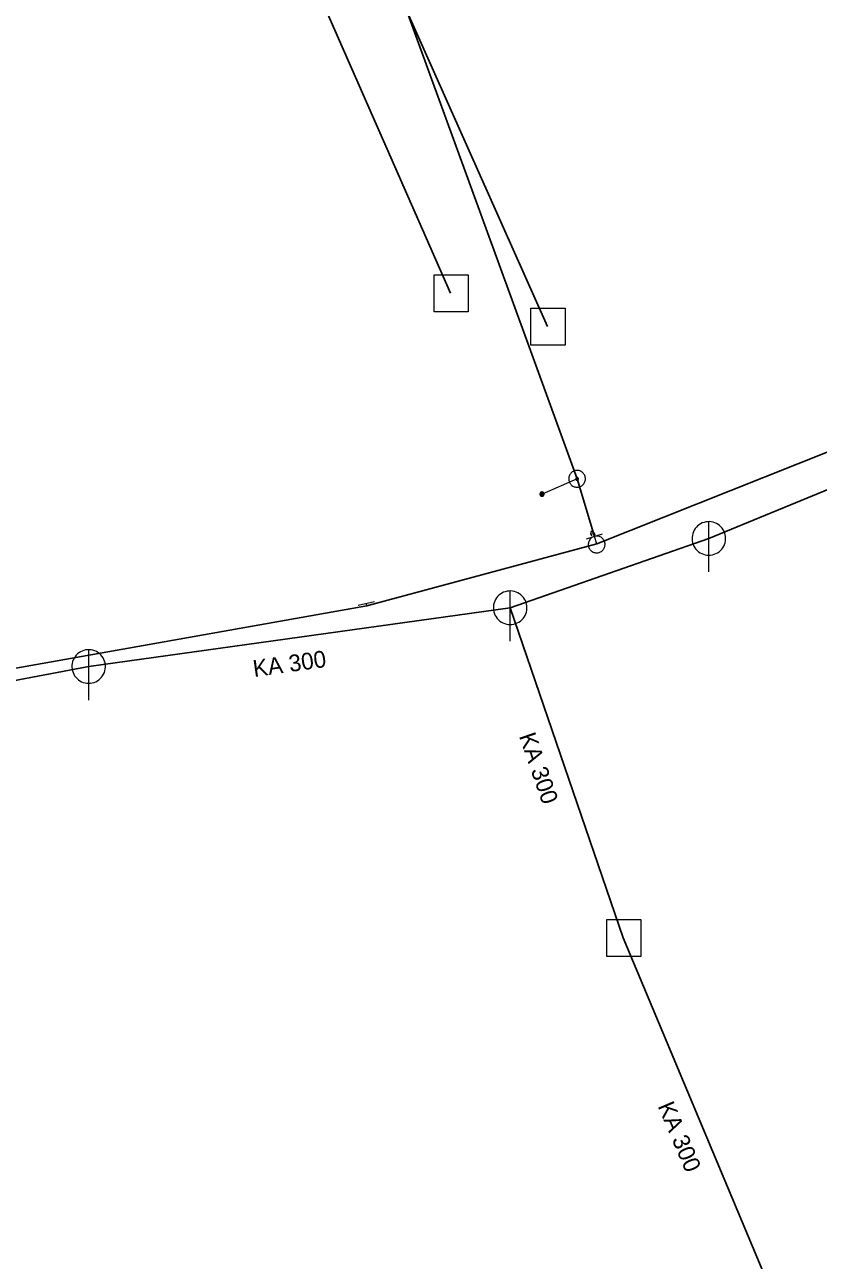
# Model space of a CAD drawing. Extents: x -690535 to -689974, y -975624 to -975325.
# Drawn here: x -690213.7 to -690166.4, y -975472.2 to -975398.6 of the extents above; entities that cross this region are included whole.
import ezdxf

# ---------------------------------------------------------------- set-up
doc = ezdxf.new("R2010")
doc.units = 0
doc.header["$LTSCALE"] = 0.4
for name, color, linetype, lineweight in [('1', 7, 'Continuous', 13), ('14', 7, 'Continuous', 25), ('17', 7, 'Continuous', 25), ('22', 7, 'Continuous', 13), ('23', 7, 'Continuous', 13), ('34', 7, 'Continuous', 13), ('47', 7, 'Continuous', 13), ('9', 7, 'Continuous', 13)]:
    doc.layers.add(name, color=color, linetype=linetype, lineweight=lineweight)

msp = doc.modelspace()

# ---------------------------------------------------------------- linework, layer by layer
at = {"layer": '14'}
for p, q in [((-690188.309, -975414.592), (-690212.881, -975358.662)), ((-690182.537, -975416.572), (-690208.285, -975358.708)), ((-690172.92, -975429.199), (-690131.567, -975412.142)), ((-690178.021, -975453.002), (-690184.76, -975433.329))]:
    msp.add_line(p, q, dxfattribs=at)
at = {"layer": '14', "lineweight": 13}
for p, q in [((-690180.772, -975425.649), (-690182.859, -975426.558)), ((-690179.591, -975429.529), (-690179.734, -975429.075)), ((-690193.294, -975433.208), (-690193.326, -975433.068))]:
    msp.add_line(p, q, dxfattribs=at)
at = {"layer": '14'}
for points in [[(-690323.219, -975469.109), (-690315.98, -975469.57), (-690290.3, -975453.039), (-690260.66, -975446.309), (-690250.27, -975443.92), (-690242.07, -975442.67), (-690236.29, -975441.84), (-690209.87, -975436.83), (-690184.76, -975433.33), (-690172.92, -975429.199)], [(-690182.905, -975499.167), (-690167.964, -975477.038), (-690178.021, -975453.002)]]:
    msp.add_lwpolyline(points, dxfattribs=at)
at = {"layer": '17'}
msp.add_line((-690179.734, -975429.075), (-690180.772, -975425.649), dxfattribs=at)
for points in [[(-690221.348, -975324.972), (-690199.401, -975376.88), (-690195.51, -975385.163), (-690183.794, -975417.35), (-690180.772, -975425.649)], [(-690179.591, -975429.529), (-690139.673, -975413.635), (-690130.226, -975409.671)], [(-690289.944, -975450.367), (-690193.294, -975433.208), (-690179.591, -975429.529)]]:
    msp.add_lwpolyline(points, dxfattribs=at)
at = {"layer": '22'}
for p, q in [((-690172.92, -975431.2), (-690172.919, -975428.2)), ((-690184.76, -975435.33), (-690184.759, -975432.33)), ((-690209.87, -975438.83), (-690209.869, -975435.83))]:
    msp.add_line(p, q, dxfattribs=at)
for points in [[(-690189.289, -975413.502), (-690187.256, -975413.502), (-690187.256, -975415.695), (-690189.289, -975415.695)], [(-690183.517, -975415.482), (-690181.485, -975415.482), (-690181.485, -975417.675), (-690183.517, -975417.675)], [(-690171.92, -975429.2), (-690171.925, -975429.091), (-690171.943, -975428.983), (-690171.973, -975428.877), (-690172.013, -975428.776), (-690172.065, -975428.679), (-690172.127, -975428.589), (-690172.199, -975428.506), (-690172.279, -975428.432), (-690172.367, -975428.366), (-690172.461, -975428.311), (-690172.561, -975428.266), (-690172.666, -975428.233), (-690172.773, -975428.211), (-690172.882, -975428.201), (-690172.992, -975428.203), (-690173.1, -975428.217), (-690173.207, -975428.242), (-690173.31, -975428.279), (-690173.408, -975428.328), (-690173.5, -975428.386), (-690173.586, -975428.455), (-690173.663, -975428.532), (-690173.732, -975428.618), (-690173.791, -975428.71), (-690173.839, -975428.808), (-690173.876, -975428.911), (-690173.902, -975429.018), (-690173.916, -975429.126), (-690173.919, -975429.236), (-690173.909, -975429.345), (-690173.888, -975429.452), (-690173.854, -975429.556), (-690173.81, -975429.656), (-690173.755, -975429.751), (-690173.689, -975429.839), (-690173.615, -975429.919), (-690173.532, -975429.991), (-690173.442, -975430.053), (-690173.346, -975430.105), (-690173.244, -975430.146), (-690173.139, -975430.176), (-690173.031, -975430.194), (-690172.921, -975430.2), (-690172.812, -975430.194), (-690172.704, -975430.176), (-690172.599, -975430.147), (-690172.497, -975430.106), (-690172.4, -975430.054), (-690172.31, -975429.992), (-690172.227, -975429.921), (-690172.152, -975429.841), (-690172.087, -975429.753), (-690172.031, -975429.659), (-690171.987, -975429.559), (-690171.953, -975429.455), (-690171.931, -975429.347), (-690171.921, -975429.238)], [(-690183.76, -975433.33), (-690183.765, -975433.221), (-690183.783, -975433.113), (-690183.813, -975433.007), (-690183.853, -975432.906), (-690183.905, -975432.809), (-690183.967, -975432.719), (-690184.039, -975432.636), (-690184.119, -975432.562), (-690184.207, -975432.496), (-690184.301, -975432.441), (-690184.401, -975432.396), (-690184.506, -975432.363), (-690184.613, -975432.341), (-690184.722, -975432.331), (-690184.832, -975432.333), (-690184.94, -975432.347), (-690185.047, -975432.372), (-690185.15, -975432.409), (-690185.248, -975432.458), (-690185.34, -975432.516), (-690185.426, -975432.585), (-690185.503, -975432.662), (-690185.572, -975432.748), (-690185.631, -975432.84), (-690185.679, -975432.938), (-690185.716, -975433.041), (-690185.742, -975433.148), (-690185.756, -975433.256), (-690185.759, -975433.366), (-690185.749, -975433.475), (-690185.728, -975433.582), (-690185.694, -975433.686), (-690185.65, -975433.786), (-690185.595, -975433.881), (-690185.529, -975433.969), (-690185.455, -975434.049), (-690185.372, -975434.121), (-690185.282, -975434.183), (-690185.186, -975434.235), (-690185.084, -975434.276), (-690184.979, -975434.306), (-690184.871, -975434.324), (-690184.761, -975434.33), (-690184.652, -975434.324), (-690184.544, -975434.306), (-690184.439, -975434.277), (-690184.337, -975434.236), (-690184.24, -975434.184), (-690184.15, -975434.122), (-690184.067, -975434.051), (-690183.992, -975433.971), (-690183.927, -975433.883), (-690183.871, -975433.789), (-690183.827, -975433.689), (-690183.793, -975433.585), (-690183.771, -975433.477), (-690183.761, -975433.368)], [(-690208.87, -975436.83), (-690208.875, -975436.721), (-690208.893, -975436.613), (-690208.923, -975436.507), (-690208.963, -975436.406), (-690209.015, -975436.309), (-690209.077, -975436.219), (-690209.149, -975436.136), (-690209.229, -975436.062), (-690209.317, -975435.996), (-690209.411, -975435.941), (-690209.511, -975435.896), (-690209.616, -975435.863), (-690209.723, -975435.841), (-690209.832, -975435.831), (-690209.942, -975435.833), (-690210.05, -975435.847), (-690210.157, -975435.872), (-690210.26, -975435.909), (-690210.358, -975435.958), (-690210.45, -975436.016), (-690210.536, -975436.085), (-690210.613, -975436.162), (-690210.682, -975436.248), (-690210.741, -975436.34), (-690210.789, -975436.438), (-690210.826, -975436.541), (-690210.852, -975436.648), (-690210.866, -975436.756), (-690210.869, -975436.866), (-690210.859, -975436.975), (-690210.838, -975437.082), (-690210.804, -975437.186), (-690210.76, -975437.286), (-690210.705, -975437.381), (-690210.639, -975437.469), (-690210.565, -975437.549), (-690210.482, -975437.621), (-690210.392, -975437.683), (-690210.296, -975437.735), (-690210.194, -975437.776), (-690210.089, -975437.806), (-690209.981, -975437.824), (-690209.871, -975437.83), (-690209.762, -975437.824), (-690209.654, -975437.806), (-690209.549, -975437.777), (-690209.447, -975437.736), (-690209.35, -975437.684), (-690209.26, -975437.622), (-690209.177, -975437.551), (-690209.102, -975437.471), (-690209.037, -975437.383), (-690208.981, -975437.289), (-690208.937, -975437.189), (-690208.903, -975437.085), (-690208.881, -975436.977), (-690208.871, -975436.868)], [(-690179, -975451.912), (-690176.968, -975451.912), (-690176.968, -975454.105), (-690179, -975454.105)]]:
    msp.add_lwpolyline(points, close=True, dxfattribs=at)
at = {"layer": '23'}
msp.add_line((-690179.75, -975428.895), (-690179.932, -975428.967), dxfattribs=at)
for points in [[(-690179.896, -975429.058), (-690179.951, -975428.919), (-690179.915, -975428.742), (-690179.769, -975428.847), (-690179.714, -975428.985)], [(-690179.141, -975429.369), (-690179.163, -975429.321), (-690179.191, -975429.275), (-690179.223, -975429.235), (-690179.258, -975429.197), (-690179.298, -975429.163), (-690179.342, -975429.133), (-690179.387, -975429.108), (-690179.435, -975429.088), (-690179.485, -975429.073), (-690179.536, -975429.063), (-690179.589, -975429.058), (-690179.642, -975429.06), (-690179.693, -975429.066), (-690179.743, -975429.079), (-690179.793, -975429.095), (-690179.842, -975429.119), (-690179.885, -975429.145), (-690179.928, -975429.178), (-690179.965, -975429.212), (-690180, -975429.252), (-690180.029, -975429.297), (-690180.054, -975429.342), (-690180.074, -975429.391), (-690180.09, -975429.44), (-690180.099, -975429.491), (-690180.103, -975429.544), (-690180.102, -975429.596), (-690180.095, -975429.648), (-690180.082, -975429.699), (-690180.066, -975429.748), (-690180.044, -975429.795), (-690180.016, -975429.84), (-690179.985, -975429.883), (-690179.949, -975429.92), (-690179.909, -975429.953), (-690179.866, -975429.983), (-690179.82, -975430.009), (-690179.771, -975430.029), (-690179.722, -975430.044)], [(-690179.928, -975429.178), (-690179.965, -975429.212), (-690180, -975429.252), (-690180.029, -975429.297), (-690180.054, -975429.342), (-690180.074, -975429.391), (-690180.09, -975429.44), (-690180.099, -975429.491), (-690180.103, -975429.544), (-690180.102, -975429.596), (-690180.095, -975429.648), (-690180.082, -975429.699), (-690180.066, -975429.748), (-690180.044, -975429.795), (-690180.016, -975429.84), (-690179.985, -975429.883), (-690179.949, -975429.92), (-690179.909, -975429.953), (-690179.866, -975429.983), (-690179.82, -975430.009), (-690179.771, -975430.029), (-690179.722, -975430.044), (-690179.671, -975430.054), (-690179.618, -975430.058), (-690179.566, -975430.058), (-690179.514, -975430.049), (-690179.464, -975430.037), (-690179.414, -975430.021), (-690179.367, -975429.998), (-690179.322, -975429.971), (-690179.28, -975429.939), (-690179.243, -975429.903), (-690179.208, -975429.863), (-690179.178, -975429.821), (-690179.154, -975429.774), (-690179.133, -975429.727), (-690179.118, -975429.677), (-690179.108, -975429.625), (-690179.104, -975429.572), (-690179.105, -975429.52)], [(-690179.722, -975430.044), (-690179.671, -975430.054), (-690179.618, -975430.058), (-690179.566, -975430.058), (-690179.514, -975430.049), (-690179.464, -975430.037), (-690179.414, -975430.021), (-690179.367, -975429.998), (-690179.322, -975429.971), (-690179.28, -975429.939), (-690179.243, -975429.903), (-690179.208, -975429.863), (-690179.178, -975429.821), (-690179.154, -975429.774), (-690179.133, -975429.727), (-690179.118, -975429.677), (-690179.108, -975429.625), (-690179.104, -975429.572), (-690179.105, -975429.52), (-690179.113, -975429.468), (-690179.124, -975429.418), (-690179.141, -975429.369), (-690179.163, -975429.321), (-690179.191, -975429.275), (-690179.223, -975429.235), (-690179.258, -975429.197), (-690179.298, -975429.163), (-690179.342, -975429.133), (-690179.387, -975429.108), (-690179.435, -975429.088), (-690179.485, -975429.073), (-690179.536, -975429.063), (-690179.589, -975429.058), (-690179.642, -975429.06), (-690179.693, -975429.066), (-690179.743, -975429.079), (-690179.793, -975429.095), (-690179.842, -975429.119), (-690179.885, -975429.145), (-690179.928, -975429.178)], [(-690179.105, -975429.52), (-690179.113, -975429.468), (-690179.124, -975429.418), (-690179.141, -975429.369)]]:
    msp.add_lwpolyline(points, dxfattribs=at)
at = {"layer": '34'}
for p, q in [((-690180.211, -975429.222), (-690179.256, -975428.928)), ((-690193.813, -975433.18), (-690192.838, -975432.956))]:
    msp.add_line(p, q, dxfattribs=at)
at = {"layer": '47'}
for points in [[(-690180.579, -975426.11), (-690180.532, -975426.087), (-690180.488, -975426.06), (-690180.447, -975426.028), (-690180.408, -975425.992), (-690180.374, -975425.952), (-690180.345, -975425.908), (-690180.321, -975425.863), (-690180.301, -975425.814), (-690180.286, -975425.765), (-690180.276, -975425.713), (-690180.272, -975425.66), (-690180.274, -975425.608), (-690180.28, -975425.557), (-690180.293, -975425.505), (-690180.31, -975425.456), (-690180.333, -975425.409), (-690180.36, -975425.365), (-690180.393, -975425.323), (-690180.428, -975425.285), (-690180.468, -975425.251), (-690180.512, -975425.222), (-690180.558, -975425.197), (-690180.606, -975425.177), (-690180.656, -975425.162), (-690180.707, -975425.153), (-690180.76, -975425.149), (-690180.812, -975425.15), (-690180.863, -975425.157), (-690180.915, -975425.17), (-690180.964, -975425.187), (-690181.011, -975425.21), (-690181.055, -975425.237), (-690181.098, -975425.269), (-690181.135, -975425.305), (-690181.169, -975425.345), (-690181.199, -975425.388), (-690181.224, -975425.434), (-690181.244, -975425.482), (-690181.258, -975425.533), (-690181.267, -975425.584), (-690181.271, -975425.637), (-690181.271, -975425.688), (-690181.263, -975425.74), (-690181.25, -975425.792), (-690181.233, -975425.841), (-690181.21, -975425.888), (-690181.183, -975425.932), (-690181.152, -975425.974), (-690181.115, -975426.012), (-690181.075, -975426.046), (-690181.032, -975426.076), (-690180.987, -975426.1), (-690180.938, -975426.12), (-690180.888, -975426.134), (-690180.836, -975426.144), (-690180.783, -975426.148), (-690180.732, -975426.147), (-690180.68, -975426.14), (-690180.628, -975426.127)], [(-690180.74, -975425.724), (-690180.732, -975425.721), (-690180.725, -975425.716), (-690180.718, -975425.711), (-690180.712, -975425.705), (-690180.706, -975425.698), (-690180.702, -975425.691), (-690180.697, -975425.684), (-690180.694, -975425.676), (-690180.692, -975425.667), (-690180.69, -975425.659), (-690180.69, -975425.65), (-690180.69, -975425.642), (-690180.691, -975425.633), (-690180.692, -975425.625), (-690180.696, -975425.617), (-690180.699, -975425.609), (-690180.704, -975425.602), (-690180.709, -975425.595), (-690180.715, -975425.589), (-690180.722, -975425.583), (-690180.729, -975425.579), (-690180.736, -975425.574), (-690180.744, -975425.571), (-690180.753, -975425.568), (-690180.761, -975425.567), (-690180.77, -975425.567), (-690180.778, -975425.567), (-690180.787, -975425.568), (-690180.795, -975425.569), (-690180.803, -975425.573), (-690180.811, -975425.576), (-690180.818, -975425.581), (-690180.825, -975425.586), (-690180.831, -975425.592), (-690180.837, -975425.599), (-690180.842, -975425.605), (-690180.846, -975425.613), (-690180.849, -975425.621), (-690180.852, -975425.63), (-690180.853, -975425.638), (-690180.853, -975425.647), (-690180.853, -975425.655), (-690180.852, -975425.664), (-690180.851, -975425.672), (-690180.847, -975425.68), (-690180.844, -975425.688), (-690180.839, -975425.695), (-690180.834, -975425.702), (-690180.828, -975425.708), (-690180.821, -975425.714), (-690180.815, -975425.719), (-690180.807, -975425.723), (-690180.799, -975425.726), (-690180.79, -975425.728), (-690180.782, -975425.73), (-690180.773, -975425.73), (-690180.765, -975425.73), (-690180.756, -975425.729), (-690180.748, -975425.728)]]:
    msp.add_lwpolyline(points, close=True, dxfattribs=at)
at = {"layer": '9'}
for points in [[(-690182.985, -975426.558), (-690182.985, -975426.571), (-690182.983, -975426.584), (-690182.98, -975426.597), (-690182.975, -975426.609), (-690182.969, -975426.621), (-690182.962, -975426.632), (-690182.954, -975426.642), (-690182.944, -975426.652), (-690182.934, -975426.66), (-690182.923, -975426.667), (-690182.911, -975426.673), (-690182.899, -975426.678), (-690182.886, -975426.681), (-690182.873, -975426.683), (-690182.86, -975426.685), (-690182.847, -975426.684), (-690182.834, -975426.682), (-690182.821, -975426.679), (-690182.809, -975426.674), (-690182.797, -975426.668), (-690182.786, -975426.661), (-690182.776, -975426.653), (-690182.766, -975426.643), (-690182.758, -975426.633), (-690182.751, -975426.622), (-690182.745, -975426.61), (-690182.74, -975426.598), (-690182.737, -975426.585), (-690182.735, -975426.572), (-690182.733, -975426.559), (-690182.734, -975426.546), (-690182.736, -975426.533), (-690182.739, -975426.52), (-690182.744, -975426.508), (-690182.75, -975426.496), (-690182.757, -975426.485), (-690182.765, -975426.475), (-690182.775, -975426.465), (-690182.785, -975426.457), (-690182.796, -975426.45), (-690182.808, -975426.444), (-690182.82, -975426.439), (-690182.833, -975426.436), (-690182.846, -975426.434), (-690182.859, -975426.433), (-690182.872, -975426.433), (-690182.885, -975426.435), (-690182.898, -975426.438), (-690182.91, -975426.443), (-690182.922, -975426.449), (-690182.933, -975426.456), (-690182.943, -975426.464), (-690182.953, -975426.474), (-690182.961, -975426.484), (-690182.968, -975426.495), (-690182.974, -975426.507), (-690182.979, -975426.519), (-690182.982, -975426.532), (-690182.984, -975426.545)], [(-690182.965, -975426.558), (-690182.966, -975426.569), (-690182.964, -975426.58), (-690182.961, -975426.591), (-690182.957, -975426.601), (-690182.952, -975426.611), (-690182.946, -975426.62), (-690182.939, -975426.629), (-690182.931, -975426.637), (-690182.922, -975426.644), (-690182.913, -975426.65), (-690182.903, -975426.655), (-690182.893, -975426.659), (-690182.882, -975426.662), (-690182.871, -975426.665), (-690182.86, -975426.665), (-690182.849, -975426.665), (-690182.838, -975426.663), (-690182.827, -975426.66), (-690182.817, -975426.656), (-690182.807, -975426.651), (-690182.798, -975426.645), (-690182.789, -975426.638), (-690182.781, -975426.63), (-690182.774, -975426.621), (-690182.768, -975426.612), (-690182.763, -975426.602), (-690182.759, -975426.592), (-690182.756, -975426.581), (-690182.754, -975426.57), (-690182.753, -975426.559), (-690182.753, -975426.548), (-690182.755, -975426.537), (-690182.758, -975426.526), (-690182.762, -975426.516), (-690182.767, -975426.506), (-690182.773, -975426.497), (-690182.78, -975426.488), (-690182.788, -975426.48), (-690182.797, -975426.473), (-690182.806, -975426.467), (-690182.816, -975426.462), (-690182.826, -975426.458), (-690182.837, -975426.455), (-690182.848, -975426.453), (-690182.859, -975426.453), (-690182.87, -975426.452), (-690182.881, -975426.454), (-690182.892, -975426.457), (-690182.902, -975426.461), (-690182.912, -975426.466), (-690182.921, -975426.472), (-690182.93, -975426.479), (-690182.938, -975426.487), (-690182.945, -975426.496), (-690182.951, -975426.505), (-690182.956, -975426.515), (-690182.96, -975426.525), (-690182.963, -975426.536), (-690182.965, -975426.547)], [(-690182.946, -975426.558), (-690182.946, -975426.567), (-690182.945, -975426.576), (-690182.942, -975426.585), (-690182.939, -975426.593), (-690182.935, -975426.601), (-690182.93, -975426.609), (-690182.924, -975426.616), (-690182.918, -975426.622), (-690182.911, -975426.628), (-690182.903, -975426.633), (-690182.895, -975426.637), (-690182.887, -975426.64), (-690182.878, -975426.643), (-690182.869, -975426.644), (-690182.86, -975426.646), (-690182.851, -975426.645), (-690182.842, -975426.644), (-690182.833, -975426.641), (-690182.825, -975426.638), (-690182.817, -975426.634), (-690182.809, -975426.629), (-690182.802, -975426.623), (-690182.796, -975426.617), (-690182.79, -975426.61), (-690182.785, -975426.602), (-690182.781, -975426.594), (-690182.778, -975426.586), (-690182.775, -975426.577), (-690182.774, -975426.568), (-690182.772, -975426.559), (-690182.773, -975426.55), (-690182.774, -975426.541), (-690182.777, -975426.532), (-690182.78, -975426.524), (-690182.784, -975426.516), (-690182.789, -975426.508), (-690182.795, -975426.501), (-690182.801, -975426.495), (-690182.808, -975426.489), (-690182.816, -975426.484), (-690182.824, -975426.48), (-690182.832, -975426.477), (-690182.841, -975426.474), (-690182.85, -975426.473), (-690182.859, -975426.472), (-690182.868, -975426.472), (-690182.877, -975426.473), (-690182.886, -975426.476), (-690182.894, -975426.479), (-690182.902, -975426.483), (-690182.91, -975426.488), (-690182.917, -975426.494), (-690182.923, -975426.5), (-690182.929, -975426.507), (-690182.934, -975426.515), (-690182.938, -975426.523), (-690182.941, -975426.531), (-690182.944, -975426.54), (-690182.945, -975426.549)], [(-690182.926, -975426.558), (-690182.926, -975426.565), (-690182.925, -975426.572), (-690182.924, -975426.579), (-690182.921, -975426.585), (-690182.918, -975426.591), (-690182.914, -975426.597), (-690182.91, -975426.603), (-690182.905, -975426.608), (-690182.899, -975426.612), (-690182.893, -975426.616), (-690182.887, -975426.619), (-690182.881, -975426.622), (-690182.874, -975426.623), (-690182.867, -975426.626), (-690182.86, -975426.626), (-690182.853, -975426.626), (-690182.846, -975426.624), (-690182.839, -975426.623), (-690182.833, -975426.62), (-690182.826, -975426.617), (-690182.821, -975426.613), (-690182.815, -975426.609), (-690182.81, -975426.604), (-690182.806, -975426.598), (-690182.802, -975426.592), (-690182.799, -975426.586), (-690182.796, -975426.58), (-690182.794, -975426.573), (-690182.793, -975426.566), (-690182.792, -975426.559), (-690182.792, -975426.552), (-690182.793, -975426.545), (-690182.795, -975426.538), (-690182.798, -975426.532), (-690182.801, -975426.525), (-690182.805, -975426.52), (-690182.809, -975426.514), (-690182.814, -975426.509), (-690182.82, -975426.505), (-690182.825, -975426.501), (-690182.832, -975426.498), (-690182.838, -975426.495), (-690182.845, -975426.493), (-690182.852, -975426.492), (-690182.859, -975426.492), (-690182.866, -975426.492), (-690182.873, -975426.492), (-690182.88, -975426.494), (-690182.886, -975426.497), (-690182.892, -975426.5), (-690182.898, -975426.504), (-690182.904, -975426.508), (-690182.909, -975426.513), (-690182.913, -975426.519), (-690182.917, -975426.524), (-690182.92, -975426.531), (-690182.923, -975426.537), (-690182.924, -975426.544), (-690182.926, -975426.551)], [(-690182.906, -975426.558), (-690182.906, -975426.563), (-690182.906, -975426.568), (-690182.905, -975426.573), (-690182.903, -975426.577), (-690182.901, -975426.582), (-690182.898, -975426.586), (-690182.895, -975426.589), (-690182.891, -975426.593), (-690182.888, -975426.596), (-690182.884, -975426.599), (-690182.879, -975426.601), (-690182.875, -975426.603), (-690182.87, -975426.604), (-690182.865, -975426.606), (-690182.86, -975426.606), (-690182.855, -975426.606), (-690182.85, -975426.605), (-690182.845, -975426.604), (-690182.841, -975426.602), (-690182.836, -975426.6), (-690182.832, -975426.597), (-690182.828, -975426.594), (-690182.825, -975426.59), (-690182.822, -975426.587), (-690182.819, -975426.583), (-690182.817, -975426.578), (-690182.815, -975426.574), (-690182.814, -975426.569), (-690182.813, -975426.564), (-690182.812, -975426.559), (-690182.812, -975426.554), (-690182.813, -975426.549), (-690182.814, -975426.544), (-690182.816, -975426.54), (-690182.818, -975426.535), (-690182.821, -975426.531), (-690182.824, -975426.527), (-690182.827, -975426.524), (-690182.831, -975426.521), (-690182.835, -975426.518), (-690182.84, -975426.516), (-690182.844, -975426.514), (-690182.849, -975426.513), (-690182.854, -975426.512), (-690182.859, -975426.512), (-690182.864, -975426.512), (-690182.869, -975426.513), (-690182.874, -975426.513), (-690182.878, -975426.515), (-690182.883, -975426.517), (-690182.887, -975426.52), (-690182.89, -975426.523), (-690182.894, -975426.526), (-690182.897, -975426.53), (-690182.9, -975426.534), (-690182.902, -975426.539), (-690182.904, -975426.543), (-690182.905, -975426.548), (-690182.906, -975426.553)], [(-690182.886, -975426.558), (-690182.886, -975426.561), (-690182.887, -975426.564), (-690182.886, -975426.566), (-690182.885, -975426.569), (-690182.884, -975426.572), (-690182.882, -975426.574), (-690182.88, -975426.576), (-690182.878, -975426.578), (-690182.876, -975426.58), (-690182.874, -975426.582), (-690182.871, -975426.584), (-690182.868, -975426.585), (-690182.866, -975426.585), (-690182.863, -975426.586), (-690182.86, -975426.586), (-690182.857, -975426.586), (-690182.854, -975426.586), (-690182.851, -975426.585), (-690182.849, -975426.584), (-690182.846, -975426.583), (-690182.844, -975426.581), (-690182.841, -975426.579), (-690182.839, -975426.577), (-690182.838, -975426.575), (-690182.836, -975426.573), (-690182.835, -975426.57), (-690182.833, -975426.567), (-690182.833, -975426.565), (-690182.832, -975426.562), (-690182.831, -975426.559), (-690182.832, -975426.556), (-690182.832, -975426.553), (-690182.833, -975426.55), (-690182.834, -975426.548), (-690182.835, -975426.545), (-690182.837, -975426.543), (-690182.838, -975426.54), (-690182.84, -975426.538), (-690182.843, -975426.537), (-690182.845, -975426.535), (-690182.848, -975426.534), (-690182.85, -975426.533), (-690182.853, -975426.532), (-690182.856, -975426.532), (-690182.859, -975426.531), (-690182.862, -975426.532), (-690182.865, -975426.531), (-690182.867, -975426.533), (-690182.87, -975426.533), (-690182.873, -975426.534), (-690182.875, -975426.536), (-690182.877, -975426.537), (-690182.879, -975426.539), (-690182.881, -975426.542), (-690182.883, -975426.544), (-690182.884, -975426.547), (-690182.885, -975426.549), (-690182.886, -975426.552), (-690182.886, -975426.555)], [(-690182.867, -975426.558), (-690182.867, -975426.56), (-690182.867, -975426.56), (-690182.866, -975426.56), (-690182.866, -975426.562), (-690182.867, -975426.563), (-690182.865, -975426.563), (-690182.865, -975426.563), (-690182.865, -975426.565), (-690182.865, -975426.565), (-690182.864, -975426.566), (-690182.862, -975426.566), (-690182.862, -975426.566), (-690182.862, -975426.567), (-690182.86, -975426.567), (-690182.86, -975426.567), (-690182.859, -975426.567), (-690182.858, -975426.567), (-690182.858, -975426.566), (-690182.857, -975426.566), (-690182.855, -975426.566), (-690182.855, -975426.565), (-690182.855, -975426.565), (-690182.854, -975426.564), (-690182.854, -975426.564), (-690182.852, -975426.563), (-690182.852, -975426.562), (-690182.851, -975426.561), (-690182.851, -975426.561), (-690182.851, -975426.56), (-690182.851, -975426.559), (-690182.851, -975426.558), (-690182.851, -975426.557), (-690182.851, -975426.557), (-690182.852, -975426.556), (-690182.852, -975426.555), (-690182.853, -975426.554), (-690182.853, -975426.554), (-690182.854, -975426.553), (-690182.854, -975426.553), (-690182.855, -975426.552), (-690182.856, -975426.552), (-690182.857, -975426.551), (-690182.857, -975426.551), (-690182.858, -975426.551), (-690182.859, -975426.551), (-690182.86, -975426.551), (-690182.861, -975426.551), (-690182.861, -975426.551), (-690182.862, -975426.552), (-690182.863, -975426.551), (-690182.864, -975426.553), (-690182.864, -975426.553), (-690182.865, -975426.553), (-690182.865, -975426.553), (-690182.866, -975426.555), (-690182.866, -975426.556), (-690182.866, -975426.557), (-690182.867, -975426.557), (-690182.867, -975426.558)]]:
    msp.add_lwpolyline(points, close=True, dxfattribs=at)

# ---------------------------------------------------------------- texts
at = {"layer": '1'}
for rotation, p in [(8, (-690200.011, -975437.46)), (289, (-690184.24, -975440.97)), (293, (-690175.982, -975463.018))]:
    msp.add_text('KA 300', height=1, rotation=rotation, dxfattribs=at).set_placement(p)

doc.saveas('drawing.dxf')
